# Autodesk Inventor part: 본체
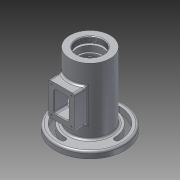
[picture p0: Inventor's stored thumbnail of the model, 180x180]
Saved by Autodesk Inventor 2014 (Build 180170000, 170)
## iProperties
Created: 2017-05
Part Number: 본체
Material: 알루미늄 6061
Document SubType Name: Modeling
Designer: Administrator
Density: 2.71 g/cm^3
Appearance: 알루미늄 - 평지
Mass: 682.081 g
Surface Area: 619.968 cm^2
Volume: 251.69 cm^3
Author: Administrator
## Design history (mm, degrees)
sketch "스케치1"
  geometry: C1 r 53 at (0, 0); 1 further point
  constraints: 1 centre point, 1 coincident
  dimensions: "d0" = 106 diameter of C1
extrude "돌출1" new body sketch "스케치1" distance "d1" = 10; taper "d2" = 0 deg
sketch "스케치2"
  geometry: C1 r 53 at (0, 0) reference; C2 r 31 at (0, 0)
  constraints: 1 centre point, 1 coincident
  dimensions: "d3" = 62 diameter of C2
extrude "돌출2" join sketch "스케치2" distance "d4" = 102; taper "d5" = 0 deg
sketch "스케치3"
  geometry: C1 r 53 at (0, 0) reference; C2 r 31 at (0, 0)
  constraints: 1 centre point, 1 coincident
  dimensions: "d6" = 62 diameter of C2
extrude "돌출3" join sketch "스케치3" distance "d7" = 3; taper "d8" = 0 deg
node "작업 평면1"
hole "구멍1" diameter "d12" = 40.376; stored, may be unused: countersink angle "d16" = 90 deg, drill point angle "d18" = 0 deg; dims "d10" = 10, "d11" = 10, "d13" = 6, "d14" = 4, "d15" = 2, "d17" = 9
sketch "스케치5"
  geometry: C1 r 20.188 at (0, 0) reference; C2 r 24 at (0, 0)
  constraints: 1 centre point, 1 coincident
  dimensions: "d19" = 48 diameter of C2
extrude "돌출4" cut sketch "스케치5" distance "d20" = 3; taper "d21" = 0 deg
sketch "스케치6"
  geometry: C1 r 24 at (0, 0) reference; C2 r 20 at (0, 0)
  constraints: 1 centre point, 1 coincident
  dimensions: "d22" = 40 diameter of C2
extrude "돌출5" cut sketch "스케치6" distance "d23" = 9; taper "d24" = 0 deg
sketch "스케치7"
  geometry: C1 r 20 at (0, 0) reference; C2 r 17.5 at (0, 0)
  constraints: 1 centre point, 1 coincident
  dimensions: "d25" = 35 diameter of C2
extrude "돌출6" cut sketch "스케치7" distance "d26" = 3.25; taper "d27" = 0 deg
sketch "스케치8"
  geometry: C1 r 17.5 at (0, 0) reference; C2 r 18.5 at (0, 0)
  constraints: 1 centre point, 1 coincident
  dimensions: "d28" = 37 diameter of C2
extrude "돌출7" cut sketch "스케치8" distance "d29" = 1.75; taper "d30" = 0 deg
sketch "스케치9"
  geometry: C1 r 18.5 at (0, 0) reference; C2 r 17.5 at (0, 0)
  constraints: 1 centre point, 1 coincident
  dimensions: "d31" = 35 diameter of C2
extrude "돌출8" cut sketch "스케치9" distance "d32" = 11; taper "d33" = 0 deg
sketch "스케치10"
  geometry: C1 r 17.5 at (0, 0) reference; C2 r 26 at (0, 0)
  constraints: 1 centre point, 1 coincident
  dimensions: "d34" = 52 diameter of C2
extrude "돌출9" cut sketch "스케치10" distance "d35" = 38; taper "d36" = 0 deg
sketch "스케치11"
  geometry: C1 r 26 at (0, 0) reference; C2 r 17.5 at (0, 0)
  constraints: 1 centre point, 1 coincident
  dimensions: "d37" = 35 diameter of C2
extrude "돌출10" cut sketch "스케치11" distance "d38" = 11; taper "d39" = 0 deg
sketch "스케치12"
  geometry: C1 r 17.5 at (0, 0) reference; C2 r 16.5 at (0, 0)
  constraints: 1 centre point, 1 coincident
  dimensions: "d40" = 33 diameter of C2
extrude "돌출11" cut sketch "스케치12" distance "d41" = 5; taper "d42" = 0 deg
sketch "스케치13"
  geometry: C1 r 16.5 at (0, 0) reference; C2 r 10 at (0, 0)
  constraints: 1 centre point, 1 coincident
  dimensions: "d43" = 20 diameter of C2
extrude "돌출12" cut sketch "스케치13" distance "d44" = 2.7; taper "d45" = 0 deg
sketch "스케치14"
  geometry: C1 r 10 at (0, 0) reference; C2 r 12.5 at (0, 0)
  constraints: 1 centre point, 1 coincident
  dimensions: "d46" = 25 diameter of C2
extrude "돌출13" cut sketch "스케치14" distance "d47" = 6.6; taper "d48" = 0 deg
sketch "스케치15"
  geometry: C1 r 12.5 at (0, 0) reference; C2 r 12.5 at (0, 0)
  constraints: 1 centre point, 1 coincident
  dimensions: "d49" = 25 diameter of C2
extrude "돌출14" cut sketch "스케치15" distance "d50" = 0.7; taper "d51" = 30 deg
node "작업 평면2"
node "작업 평면3"
sketch "스케치17"
  geometry: L1 (53, 10)-(53, 0) reference; L2 (53, 0)-(31, 0) reference; L3 (31, 0)-(31, -3) reference; L4 (31, -3)-(-31, -3) reference; L5 (-31, -3)-(-31, 0) reference; L6 (-31, 0)-(-53, 0) reference; L7 (-53, 0)-(-53, 10) reference; L8 (-53, 10)-(-31, 10) reference; L9 (-31, 10)-(-31, 112) reference; L10 (-31, 112)-(-20.188, 112) reference; L11 (-20.188, 112)-(-20.188, 103) reference; L12 (-20.188, 103)-(-24, 103) reference; L13 (-24, 103)-(-24, 100) reference; L14 (-24, 100)-(-20, 100) reference; L15 (-20, 100)-(-20, 91) reference; L16 (-20, 91)-(-17.5, 91) reference; L17 (-17.5, 91)-(-17.5, 87.75) reference; L18 (-17.5, 87.75)-(-18.5, 87.75) reference; L19 (-18.5, 87.75)-(-18.5, 86) reference; L20 (-18.5, 86)-(-17.5, 86) reference; L21 (-17.5, 86)-(-17.5, 75) reference; L22 (-17.5, 75)-(-26, 75) reference; L23 (-26, 75)-(-26, 37) reference; L24 (-26, 37)-(-17.5, 37) reference; L25 (-17.5, 37)-(-17.5, 26) reference; L26 (-17.5, 26)-(-16.5, 26) reference; L27 (-16.5, 26)-(-16.5, 21) reference; L28 (-16.5, 21)-(-10, 21) reference; L29 (-10, 21)-(-10, 18.3) reference; L30 (-10, 18.3)-(-12.5, 18.3) reference; L31 (-12.5, 18.3)-(-12.5, 11.7) reference; L32 (-12.5, 11.7)-(-12.904, 11) reference; L33 (-12.904, 11)-(12.904, 11) reference; L34 (12.904, 11)-(12.5, 11.7) reference; L35 (12.5, 11.7)-(12.5, 18.3) reference; L36 (12.5, 18.3)-(10, 18.3) reference; L37 (10, 18.3)-(10, 21) reference; L38 (10, 21)-(16.5, 21) reference; L39 (16.5, 21)-(16.5, 26) reference; L40 (16.5, 26)-(17.5, 26) reference; L41 (17.5, 26)-(17.5, 37) reference; L42 (17.5, 37)-(26, 37) reference; L43 (26, 37)-(26, 75) reference; L44 (26, 75)-(17.5, 75) reference; L45 (17.5, 75)-(17.5, 86) reference; L46 (17.5, 86)-(18.5, 86) reference; L47 (18.5, 86)-(18.5, 87.75) reference; L48 (18.5, 87.75)-(17.5, 87.75) reference; L49 (17.5, 87.75)-(17.5, 91) reference; L50 (17.5, 91)-(20, 91) reference; L51 (20, 91)-(20, 100) reference; L52 (20, 100)-(24, 100) reference; L53 (24, 100)-(24, 103) reference; L54 (24, 103)-(20.188, 103) reference; L55 (20.188, 103)-(20.188, 112) reference; L56 (20.188, 112)-(31, 112) reference; L57 (31, 112)-(31, 10) reference; L58 (31, 10)-(53, 10) reference; L59 (0, 11)-(0, -3); L60 (0, 11)-(16, 11); L61 (0, -3)-(22, -3); L62 (16, 11)-(22, -3); 1 further point
  constraints: 8 end point, 2 midpoint, 2 point on line
  dimensions: "d54" = 44 diameter of L61.end L59; "d55" = 32 diameter of L60.end L59
revolve "회전1" sketch "스케치17" stored, may be unused: angle "d56" = 90 deg
node "작업 평면4"
node "작업 평면5"
sketch "스케치19"
  geometry: L1 (-29.547, 0)-(-29.547, 10) reference; L2 (-29.547, 10)-(29.547, 10) reference; L3 (29.547, 10)-(29.547, 0) reference; L4 (29.547, 0)-(-29.547, 0) reference; L5 (31, 112)-(-31, 112) reference; L6 (20, 81)-(-20, 81); L7 (-20, 81)-(-20, 31); L8 (-20, 31)-(20, 31); L9 (20, 31)-(20, 81); L10 (20, 81)-(-20, 31); L11 (-20, 81)-(20, 31); 4 further points
  constraints: 12 end point, 4 midpoint, 2 parallel, 1 horizontal, 1 perpendicular, 1 vertical alignment
  dimensions: "d62" = 56 distance from line of L5 point (0, 56); "d63" = 50 distance of L8.end L6.start; "d64" = 40 distance of L6.start L6.end
extrude "돌출15" join sketch "스케치19" stored distance "d65" = 0.7; taper "d66" = 0 deg
sketch "스케치20"
  geometry: L1 (-20, 81)-(-20, 31) reference; L2 (-20, 31)-(20, 31) reference; L3 (20, 31)-(20, 81) reference; L4 (20, 81)-(-20, 81) reference; L5 (11, 72)-(11, 40); L6 (11, 40)-(-11, 40); L7 (-11, 40)-(-11, 72); L8 (-11, 72)-(11, 72); 3 further points
  constraints: 8 end point, 2 midpoint, 1 vertical alignment, 3 other
  dimensions: "d68" = 32 distance of L5.start L5.end; "d69" = 22 distance of L7.end L5.start (derived)
extrude "돌출16" cut sketch "스케치20" stored distance "d70" = 0.7; taper "d71" = 0 deg
hole "구멍2" diameter "d74" = 2.459; stored, may be unused: countersink angle "d78" = 90 deg, drill point angle "d80" = 118 deg; dims "d72" = 4.5, "d73" = 4.5, "d75" = 6, "d76" = 4, "d77" = 2, "d79" = 8
sketch "스케치22"
  geometry: C1 r 31 at (0, 0) reference; C2 r 53 at (0, 0) reference; A1 r 41.5 centre (0, 0) between (41.5, 0) and (0, -41.5); A2 r 37.5 centre (0, 0) between (37.5, 0) and (0, 37.5); A3 r 4 centre (41.5, 0) between (45.5, 0) and (37.5, 0); A4 r 4 centre (0, -41.5) between (0, -37.5) and (0, -45.5); A5 r 4 centre (0, 41.5) between (0, 37.5) and (0, 45.5); A6 r 4 centre (-41.5, 0) between (-45.5, 0) and (-37.5, 0); A7 r 45.5 centre (0, 0) between (0, 45.5) and (-45.5, 0); A8 r 37.5 centre (0, 0) between (0, 37.5) and (-37.5, 0); A9 r 37.5 centre (0, 0) between (0, -37.5) and (37.5, 0); A10 r 45.5 centre (0, 0) between (0, -45.5) and (45.5, 0)
  constraints: 22 point on circle, 10 centre point, 6 coincident, 2 horizontal alignment, 2 vertical alignment, 1 tangent
  dimensions: "d87" = 83 diameter of A1; "d88" = 75 diameter of A2; "d89" = 8 diameter of A3; "d90" = 8 diameter of A4; "d91" = 8 diameter of A5; "d92" = 8 diameter of A6; "d93" = 45.5 radius of A7
extrude "돌출17" cut sketch "스케치22" distance "d94" = 10; taper "d95" = 0 deg
node "작업 평면6"
sketch "스케치23"
  geometry: L1 (-16.613, 37)-(16.613, 37) reference; L2 (16.613, 37)-(16.613, 75) reference; L3 (16.613, 75)-(-16.613, 75) reference; L4 (-16.613, 75)-(-16.613, 37) reference; L5 (49.082, 10)-(49.082, 0) reference; L6 (49.082, 0)-(40.869, 0) reference; L7 (40.869, 0)-(40.869, 10) reference; L8 (40.869, 10)-(49.082, 10) reference; L9 (-49.082, 0)-(-49.082, 10) reference; L10 (-49.082, 10)-(-23.685, 10) reference; L11 (-23.685, 10)-(-23.685, 112) reference; L12 (-23.685, 112)-(-2.749, 112) reference; L13 (-2.749, 112)-(-2.749, 103) reference; L14 (-2.749, 103)-(-13.266, 103) reference; L15 (-13.266, 103)-(-13.266, 100) reference; L16 (-13.266, 100)-(0, 100) reference; L17 (0, 91)-(0, 100) reference; L18 (-23.685, 0)-(-49.082, 0) reference; L19 (-23.685, -3)-(-23.685, 0) reference; L20 (-9.165, -3)-(-23.685, -3) reference; L21 (23.685, -3)-(9.165, -3) reference; L22 (23.685, 0)-(23.685, -3) reference; L23 (31.721, 0)-(23.685, 0) reference; L24 (31.721, 10)-(31.721, 0) reference; L25 (23.685, 10)-(31.721, 10) reference; L26 (23.685, 31)-(23.685, 10) reference; L27 (44, 31)-(23.685, 31) reference; L28 (44, 81)-(44, 31) reference; L29 (23.685, 81)-(44, 81) reference; L30 (23.685, 112)-(23.685, 81) reference; L31 (2.749, 112)-(23.685, 112) reference; L32 (2.749, 103)-(2.749, 112) reference; L33 (13.266, 103)-(2.749, 103) reference; L34 (13.266, 100)-(13.266, 103) reference; L35 (0, 100)-(13.266, 100) reference; L36 (23.685, 81)-(23.685, 31) reference; 2 further points
  constraints: 1 horizontal alignment, 1 other
  dimensions: "d97" = 56 distance from line of L31 point (36, 56); "d98" = 8 distance from line of point (36, 56) L28
feature "엠보싱1" sketch "스케치23" dims "d99" = 0.5, "d100" = 0
fillet "모깎기1" dims "d101" = 3
fillet "모깎기2" dims "d102" = 0.3
fillet "모깎기3" dims "d103" = 3
fillet "모깎기4" dims "d104" = 3
fillet "모깎기5" dims "d105" = 3
fillet "모깎기6" dims "d106" = 3
chamfer "모따기1" distance "d107" = 1; stored, may be unused: second distance "d108" = 2, angle "d109" = 45 deg
fillet "모깎기7" dims "d113" = 3
fillet "모깎기8" dims "d114" = 0.3
fillet "모깎기9" dims "d115" = 3
fillet "모깎기10" dims "d116" = 3
chamfer "모따기3" distance "d117" = 1; stored, may be unused: second distance "d118" = 2, angle "d119" = 45 deg
node "솔리드1"
pattern_linear "직사각형 패턴1" dims "d83" = 41, "d86" = 31
node "절단 모서리 투영3"
node "절단 모서리 투영5"
node "절단 모서리 투영6"
other parameters: "d9" = 0, "d52" = 0, "d53" = 0, "d57" = -31, "d61" = -44
